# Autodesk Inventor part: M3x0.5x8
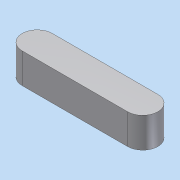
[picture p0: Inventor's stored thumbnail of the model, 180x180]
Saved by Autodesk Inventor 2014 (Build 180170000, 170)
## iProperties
Company: 한국ATC센터
Created: 2009-02
Part Number: M3x0.5x8
Document SubType Name: Modeling
Designer: KYOUNG IL JANG
Density: 1 g/cm^3
Mass: 0.274265 g
Surface Area: 2.99398 cm^2
Volume: 0.274265 cm^3
Vendor: CBT Solutions
Material: 일반
Appearance: 기본값
Author: KYOUNG IL JANG
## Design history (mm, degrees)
sketch "스케치1"
  geometry: L1 (0, 2)-(14, 2); L2 (0, -2)-(14, -2); A1 r 2 centre (0, 0) between (0, 2) and (0, -2); A2 r 2 centre (14, 0) between (14, -2) and (14, 2); 1 further point
  constraints: 4 end point, 4 point on circle, 3 tangent, 2 centre point, 1 coincident, 1 equal radius, 1 horizontal alignment, 1 parallel
  dimensions: "d0" = 4 distance between parallel lines of L2 L1; "d1" = 18 dimension on A2 A1
extrude "돌출1" new body sketch "스케치1" distance "d2" = 4; taper "d3" = 0 deg
node "솔리드1"
